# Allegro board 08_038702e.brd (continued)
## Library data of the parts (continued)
SW1 = SWSPST4PIN_V2: User Part Number: UPN; Tolerance: N/A; alternate symbols: (); part number: SWSPST4PIN_V2_SM-7914J-1-000E,E011086,SWSMSQ197H165; tolerance: N/A
T1-T8 = XFMRTCMXXXX_V3: Tolerance: N/A; User Part Number: UPN; alternate symbols: (); part number: XFMRTCMXXXX_V3_SM-TCM1-63AX+,E018203,TSML150W160H160; tolerance: N/A
TP2 = NCTESTPAD: Tolerance: N/A; User Part Number: UPN; alternate symbols: (); part number: NCTESTPAD_SM-TESTPAD,E012884,TPSMC30; tolerance: N/A
U1 = ICXC7Z035: Tolerance: N/A; User Part Number: UPN; alternate symbols: (); part number: ICXC7Z035_SM-XC7Z035-L2FBG676I,E022235,FBGA676; tolerance: N/A
U2 U3 = ICMT41K256M16: User Part Number: UPN; Tolerance: N/A; alternate symbols: (); part number: ICMT41K256M16_SM-MT41K256M16TW-107:P,E025442,FBGA96_C; tolerance: N/A
U4 = ADP5135: Tolerance: N/A; User Part Number: UPN; alternate symbols: (); part number: ADP5135_SM-ADP5135,E019805,QFN24_4X4_PAD2_6X2_6; tolerance: N/A
U5 = ADG772: User Part Number: UPN; Tolerance: N/A; alternate symbols: (); part number: ADG772_SM-ADG772BCPZ,E010354,QFN10_1_6X1_3; tolerance: N/A
U6 = ADP7102: Tolerance: N/A; User Part Number: UPN; alternate symbols: (); part number: ADP7102_SM-ADP7102ACPZ-2.5,E021467,QFN8_3X3_PAD2_44X1_7; tolerance: N/A
U7 = ADM1166: User Part Number: UPN; Tolerance: N/A; alternate symbols: (); part number: ADM1166_SM-ADM1166ACPZ,E016939,QFN40_6X6_PAD4_6X4_6; tolerance: N/A
U8 = ADM7160: User Part Number: UPN; Tolerance: N/A; alternate symbols: (); part number: ADM7160_SM-ADM7160AUJZ-1.8,E018469,TSOT-5; tolerance: N/A
U9 = ADP7104: Tolerance: N/A; User Part Number: UPN; alternate symbols: (); part number: ADP7104_SM-ADP7104ACPZ-3.3-R7,E014912,QFN8_3X3_PAD2_44X1_7; tolerance: N/A
U10 = IC88E151X: User Part Number: UPN; Tolerance: N/A; alternate symbols: (); part number: IC88E151X_SM-88E1512-56QFN,E018914,QFN56_8X8_PAD4_37X4_37; tolerance: N/A
U11 = ICTXS02612RTW: User Part Number: UPN; Tolerance: N/A; alternate symbols: (); part number: ICTXS02612RTW_SM-TXS02612RTWR,E021332,QFN24_4X4_PAD2_5X2_5; tolerance: N/A
U13 = ICN25Q256A_V2: User Part Number: UPN; Tolerance: N/A; alternate symbols: (); part number: ICN25Q256A_V2_SM-N25Q256A11E1240,E023338,TBGA24; tolerance: N/A
U14 = ICTPS51206: Tolerance: N/A; User Part Number: UPN; alternate symbols: (); part number: ICTPS51206_SM-TPS51206DSQR,E021346,SON10_2X2_PAD1_5X0_9; tolerance: N/A
U15 = ICUSB3320C: Tolerance: N/A; User Part Number: UPN; alternate symbols: (); part number: ICUSB3320C_SM-USB3320C-EZK,E021334,QFN32_5X5_PAD3_3X3_3; tolerance: N/A
U16 = DIO6P_V8: User Part Number: UPN; Tolerance: N/A; alternate symbols: (); part number: DIO6P_V8_SM-CDSOT23-SR208,20V,N/A,E021337,SOT23_6-2; tolerance: N/A
U17 = AD9361: Tolerance: N/A; User Part Number: UPN; alternate symbols: (); part number: AD9361_SM-AD9361BBCZ,E011827,BGA144; tolerance: N/A
U18 = ADP238X: User Part Number: UPN; Tolerance: N/A; alternate symbols: (); part number: ADP238X_SM-ADP2386ACPZN,E012985,QFN24_4X4_2PAD; tolerance: N/A
U19 U20 = ADP1754: Tolerance: N/A; User Part Number: UPN; alternate symbols: (); part number: ADP1754_SM-ADP1754ACPZ-1.3,E022696,QFN16_4X4_PAD2_1X2_1; tolerance: N/A
U21 = CMOSTCA9517: Tolerance: N/A; User Part Number: UPN; alternate symbols: (); part number: CMOSTCA9517_SM-TCA9517DGKR,E022173,MSOP8; tolerance: N/A
U22 = ICFXL4T245: Tolerance: N/A; User Part Number: UPN; alternate symbols: (); part number: ICFXL4T245_SM-FXL4T245BQX,E021654,DQFN14_3X2_5_PAD1_65X1_15; tolerance: N/A
U23 = ADP7118_V2: User Part Number: UPN; Tolerance: N/A; alternate symbols: (); part number: ADP7118_V2_SM-ADP7118AUJZ-3.3,E021874,TSOT-5; tolerance: N/A
U24 = AD7291: User Part Number: UPN; Tolerance: N/A; alternate symbols: (); part number: AD7291_SM-AD7291BCPZ,E017361,QFN20_4X4_PAD2_6X2_6; tolerance: N/A
Y1 = XTALOSC4P_V7: Tolerance: N/A; User Part Number: UPN; alternate symbols: (); part number: XTALOSC4P_V7_SM-33.333MEGHZ,E024048,YSML98W79H35; tolerance: N/A
Y2 = XTAL4PIN_V3: Tolerance: +/-20PPM; User Part Number: UPN; alternate symbols: (); part number: XTAL4PIN_V3_SM-25MEGHZ,E023420,YSML126W98H39; tolerance: +/-20PPM
Y3 = XTALOSC4P_V7: Tolerance: N/A; User Part Number: UPN; alternate symbols: (); part number: XTALOSC4P_V7_SM-24MEGHZ,E022374,YSML98W79H35; tolerance: N/A
Y4 = XTALOSC4P_V21: Tolerance: N/A; User Part Number: UPN; alternate symbols: (); part number: XTALOSC4P_V21_SM-40MEGHZ,E020493,YSML126W98H47; tolerance: N/A

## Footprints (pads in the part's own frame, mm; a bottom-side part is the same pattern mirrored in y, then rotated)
BGA144
  round 0.356 smd: A1(-4.4,-4.4) A2(-4.4,-3.6) A3(-4.4,-2.8) A4(-4.4,-2) A5(-4.4,-1.2) A6(-4.4,-0.4) A7(-4.4,0.4) A8(-4.4,1.2) A9(-4.4,2) A10(-4.4,2.8) A11(-4.4,3.6) A12(-4.4,4.4) B1(-3.6,-4.4) B2(-3.6,-3.6) B3(-3.6,-2.8) B4(-3.6,-2) B5(-3.6,-1.2) B6(-3.6,-0.4) B7(-3.6,0.4) B8(-3.6,1.2) B9(-3.6,2) B10(-3.6,2.8) B11(-3.6,3.6) B12(-3.6,4.4) C1(-2.8,-4.4) C2(-2.8,-3.6) C3(-2.8,-2.8) C4(-2.8,-2) C5(-2.8,-1.2) C6(-2.8,-0.4) C7(-2.8,0.4) C8(-2.8,1.2) C9(-2.8,2) C10(-2.8,2.8) C11(-2.8,3.6) C12(-2.8,4.4) D1(-2,-4.4) D2(-2,-3.6) D3(-2,-2.8) D4(-2,-2) D5(-2,-1.2) D6(-2,-0.4) D7(-2,0.4) D8(-2,1.2) D9(-2,2) D10(-2,2.8) D11(-2,3.6) D12(-2,4.4) E1(-1.2,-4.4) E2(-1.2,-3.6) E3(-1.2,-2.8) E4(-1.2,-2) E5(-1.2,-1.2) E6(-1.2,-0.4) E7(-1.2,0.4) E8(-1.2,1.2) E9(-1.2,2) E10(-1.2,2.8) E11(-1.2,3.6) E12(-1.2,4.4) F1(-0.4,-4.4) F2(-0.4,-3.6) F3(-0.4,-2.8) F4(-0.4,-2) F5(-0.4,-1.2) F6(-0.4,-0.4) F7(-0.4,0.4) F8(-0.4,1.2) F9(-0.4,2) F10(-0.4,2.8) F11(-0.4,3.6) F12(-0.4,4.4) G1(0.4,-4.4) G2(0.4,-3.6) G3(0.4,-2.8) G4(0.4,-2) G5(0.4,-1.2) G6(0.4,-0.4) G7(0.4,0.4) G8(0.4,1.2) G9(0.4,2) G10(0.4,2.8) G11(0.4,3.6) G12(0.4,4.4) H1(1.2,-4.4) H2(1.2,-3.6) H3(1.2,-2.8) H4(1.2,-2) H5(1.2,-1.2) H6(1.2,-0.4) H7(1.2,0.4) H8(1.2,1.2) H9(1.2,2) H10(1.2,2.8) H11(1.2,3.6) H12(1.2,4.4) J1(2,-4.4) J2(2,-3.6) J3(2,-2.8) J4(2,-2) J5(2,-1.2) J6(2,-0.4) J7(2,0.4) J8(2,1.2) J9(2,2) J10(2,2.8) J11(2,3.6) J12(2,4.4) K1(2.8,-4.4) K2(2.8,-3.6) K3(2.8,-2.8) K4(2.8,-2) K5(2.8,-1.2) K6(2.8,-0.4) K7(2.8,0.4) K8(2.8,1.2) K9(2.8,2) K10(2.8,2.8) K11(2.8,3.6) K12(2.8,4.4) L1(3.6,-4.4) L2(3.6,-3.6) L3(3.6,-2.8) L4(3.6,-2) L5(3.6,-1.2) L6(3.6,-0.4) L7(3.6,0.4) L8(3.6,1.2) L9(3.6,2) L10(3.6,2.8) L11(3.6,3.6) L12(3.6,4.4) M1(4.4,-4.4) M2(4.4,-3.6) M3(4.4,-2.8) M4(4.4,-2) M5(4.4,-1.2) M6(4.4,-0.4) M7(4.4,0.4) M8(4.4,1.2) M9(4.4,2) M10(4.4,2.8) M11(4.4,3.6) M12(4.4,4.4)
C0201
  rect 0.305x0.406 smd: 1(-0.318,0) 2(0.318,0)
C0402
  rect 0.889x0.813 smd: 1(-0.635,0) 2(0.635,0)
C0603
  rect 1.092x1.194 smd: 1(-0.851,0) 2(0.851,0)
C0805
  rect 1.295x1.6 smd: 1(-0.953,0) 2(0.953,0)
C0805H60
  rect 1.295x1.6 smd: 1(-0.953,0) 2(0.953,0)
C1206H71
  rect 1.6x2.007 smd: 1(-1.397,0) 2(1.397,0)
CNFCI61082-101400
  round 2.21 hole 1.194 unplated: (-22.1,0)
  round 1.905 hole 0.787 unplated: (22.1,0)
  rect 0.508x2.007 smd: 1(-19.6,-2.2) 2(-19.6,2.2) 3(-18.8,-2.2) 4(-18.8,2.2) 5(-18,-2.2) 6(-18,2.2) 7(-17.2,-2.2) 8(-17.2,2.2) 9(-16.4,-2.2) 10(-16.4,2.2) 11(-15.6,-2.2) 12(-15.6,2.2) 13(-14.8,-2.2) 14(-14.8,2.2) 15(-14,-2.2) 16(-14,2.2) 17(-13.2,-2.2) 18(-13.2,2.2) 19(-12.4,-2.2) 20(-12.4,2.2) 21(-11.6,-2.2) 22(-11.6,2.2) 23(-10.8,-2.2) 24(-10.8,2.2) 25(-10,-2.2) 26(-10,2.2) 27(-9.2,-2.2) 28(-9.2,2.2) 29(-8.4,-2.2) 30(-8.4,2.2) 31(-7.6,-2.2) 32(-7.6,2.2) 33(-6.8,-2.2) 34(-6.8,2.2) 35(-6,-2.2) 36(-6,2.2) 37(-5.2,-2.2) 38(-5.2,2.2) 39(-4.4,-2.2) 40(-4.4,2.2) 41(-3.6,-2.2) 42(-3.6,2.2) 43(-2.8,-2.2) 44(-2.8,2.2) 45(-2,-2.2) 46(-2,2.2) 47(-1.2,-2.2) 48(-1.2,2.2) 49(-0.4,-2.2) 50(-0.4,2.2) 51(0.4,-2.2) 52(0.4,2.2) 53(1.2,-2.2) 54(1.2,2.2) 55(2,-2.2) 56(2,2.2) 57(2.8,-2.2) 58(2.8,2.2) 59(3.6,-2.2) 60(3.6,2.2) 61(4.4,-2.2) 62(4.4,2.2) 63(5.2,-2.2) 64(5.2,2.2) 65(6,-2.2) 66(6,2.2) 67(6.8,-2.2) 68(6.8,2.2) 69(7.6,-2.2) 70(7.6,2.2) 71(8.4,-2.2) 72(8.4,2.2) 73(9.2,-2.2) 74(9.2,2.2) 75(10,-2.2) 76(10,2.2) 77(10.8,-2.2) 78(10.8,2.2) 79(11.6,-2.2) 80(11.6,2.2) 81(12.4,-2.2) 82(12.4,2.2) 83(13.2,-2.2) 84(13.2,2.2) 85(14,-2.2) 86(14,2.2) 87(14.8,-2.2) 88(14.8,2.2) 89(15.6,-2.2) 90(15.6,2.2) 91(16.4,-2.2) 92(16.4,2.2) 93(17.2,-2.2) 94(17.2,2.2) 95(18,-2.2) 96(18,2.2) 97(18.8,-2.2) 98(18.8,2.2) 99(19.6,-2.2) 100(19.6,2.2)
CNHIROSE-U_FL-R-SMT-1
  rect 0.991x1.041 smd: 1(0,-1.521)
  rect 1.041x2.21 smd: 2(-1.471,0) 3(1.471,0)
CNHIROSEDM3CS-SF
  rect 2.007x0.711 smd: 1(-6.204,-3.2) 2(-6.204,-2.1) 3(-6.204,-1) 4(-6.204,0.1) 5(-6.204,1.2) 6(-6.204,2.3) 7(-6.204,3.4) 8(-6.204,4.5)
  rect 1.397x2.692 smd: 9(6.5,-1.8) GND3(6.5,3.1)
  rect 2.591x1.499 smd: GND1(-5.7,-6.75)
  rect 1.194x1.194 smd: GND2(6.6,-4.85)
  rect 2.591x0.991 smd: GND4(-5.7,6.6)
CNTE5147733-4
  rect 1.524x2.286 smd: A1(-5.08,-4.52) A2(-2.54,-4.52) A3(0,-4.52) A4(2.54,-4.52) A5(5.08,-4.52) B1(-5.08,4.52) B2(-2.54,4.52) B3(0,4.52) B4(2.54,4.52) B5(5.08,4.52)
CPLSML287W169H118
  rect 2.388x2.896 smd: N(3.044,0) P(-3.044,0)
DQFN14_3X2_5_PAD1_65X1_15
  oval 0.914x0.254 smd: 1(-1.557,-0.25) 7(1.557,-0.25) 8(1.557,0.25) 14(-1.557,0.25)
  oval 0.254x0.914 smd: 2(-1,-1.307) 3(-0.5,-1.307) 4(0,-1.307) 5(0.5,-1.307) 6(1,-1.307) 9(1,1.307) 10(0.5,1.307) 11(0,1.307) 12(-0.5,1.307) 13(-1,1.307)
  rect 1.651x1.143 smd: PAD(0,0)
FBGA96_C
  round 0.381 smd: A1(-6,-3.2) A2(-6,-2.4) A3(-6,-1.6) A7(-6,1.6) A8(-6,2.4) A9(-6,3.2) B1(-5.2,-3.2) B2(-5.2,-2.4) B3(-5.2,-1.6) B7(-5.2,1.6) B8(-5.2,2.4) B9(-5.2,3.2) C1(-4.4,-3.2) C2(-4.4,-2.4) C3(-4.4,-1.6) C7(-4.4,1.6) C8(-4.4,2.4) C9(-4.4,3.2) D1(-3.6,-3.2) D2(-3.6,-2.4) D3(-3.6,-1.6) D7(-3.6,1.6) D8(-3.6,2.4) D9(-3.6,3.2) E1(-2.8,-3.2) E2(-2.8,-2.4) E3(-2.8,-1.6) E7(-2.8,1.6) E8(-2.8,2.4) E9(-2.8,3.2) F1(-2,-3.2) F2(-2,-2.4) F3(-2,-1.6) F7(-2,1.6) F8(-2,2.4) F9(-2,3.2) G1(-1.2,-3.2) G2(-1.2,-2.4) G3(-1.2,-1.6) G7(-1.2,1.6) G8(-1.2,2.4) G9(-1.2,3.2) H1(-0.4,-3.2) H2(-0.4,-2.4) H3(-0.4,-1.6) H7(-0.4,1.6) H8(-0.4,2.4) H9(-0.4,3.2) J1(0.4,-3.2) J2(0.4,-2.4) J3(0.4,-1.6) J7(0.4,1.6) J8(0.4,2.4) J9(0.4,3.2) K1(1.2,-3.2) K2(1.2,-2.4) K3(1.2,-1.6) K7(1.2,1.6) K8(1.2,2.4) K9(1.2,3.2) L1(2,-3.2) L2(2,-2.4) L3(2,-1.6) L7(2,1.6) L8(2,2.4) L9(2,3.2) M1(2.8,-3.2) M2(2.8,-2.4) M3(2.8,-1.6) M7(2.8,1.6) M8(2.8,2.4) M9(2.8,3.2) N1(3.6,-3.2) N2(3.6,-2.4) N3(3.6,-1.6) N7(3.6,1.6) N8(3.6,2.4) N9(3.6,3.2) P1(4.4,-3.2) P2(4.4,-2.4) P3(4.4,-1.6) P7(4.4,1.6) P8(4.4,2.4) P9(4.4,3.2) R1(5.2,-3.2) R2(5.2,-2.4) R3(5.2,-1.6) R7(5.2,1.6) R8(5.2,2.4) R9(5.2,3.2) T1(6,-3.2) T2(6,-2.4) T3(6,-1.6) T7(6,1.6) T8(6,2.4) T9(6,3.2)
FBGA676
  round 0.457 smd: A1(-12.5,-12.5) A2(-12.5,-11.5) A3(-12.5,-10.5) A4(-12.5,-9.5) A5(-12.5,-8.5) A6(-12.5,-7.5) A7(-12.5,-6.5) A8(-12.5,-5.5) A9(-12.5,-4.5) A10(-12.5,-3.5) A11(-12.5,-2.5) A12(-12.5,-1.5) A13(-12.5,-0.5) A14(-12.5,0.5) A15(-12.5,1.5) A16(-12.5,2.5) A17(-12.5,3.5) A18(-12.5,4.5) A19(-12.5,5.5) A20(-12.5,6.5) A21(-12.5,7.5) A22(-12.5,8.5) A23(-12.5,9.5) A24(-12.5,10.5) A25(-12.5,11.5) A26(-12.5,12.5) AA1(7.5,-12.5) AA2(7.5,-11.5) AA3(7.5,-10.5) AA4(7.5,-9.5) AA5(7.5,-8.5) AA6(7.5,-7.5) AA7(7.5,-6.5) AA8(7.5,-5.5) AA9(7.5,-4.5) AA10(7.5,-3.5) AA11(7.5,-2.5) AA12(7.5,-1.5) AA13(7.5,-0.5) AA14(7.5,0.5) AA15(7.5,1.5) AA16(7.5,2.5) AA17(7.5,3.5) AA18(7.5,4.5) AA19(7.5,5.5) AA20(7.5,6.5) AA21(7.5,7.5) AA22(7.5,8.5) AA23(7.5,9.5) AA24(7.5,10.5) AA25(7.5,11.5) AA26(7.5,12.5) AB1(8.5,-12.5) AB2(8.5,-11.5) AB3(8.5,-10.5) AB4(8.5,-9.5) AB5(8.5,-8.5) AB6(8.5,-7.5) AB7(8.5,-6.5) AB8(8.5,-5.5) AB9(8.5,-4.5) AB10(8.5,-3.5) AB11(8.5,-2.5) AB12(8.5,-1.5) AB13(8.5,-0.5) AB14(8.5,0.5) AB15(8.5,1.5) AB16(8.5,2.5) AB17(8.5,3.5) AB18(8.5,4.5) AB19(8.5,5.5) AB20(8.5,6.5) AB21(8.5,7.5) AB22(8.5,8.5) AB23(8.5,9.5) AB24(8.5,10.5) AB25(8.5,11.5) AB26(8.5,12.5) AC1(9.5,-12.5) AC2(9.5,-11.5) AC3(9.5,-10.5) AC4(9.5,-9.5) AC5(9.5,-8.5) AC6(9.5,-7.5) AC7(9.5,-6.5) AC8(9.5,-5.5) AC9(9.5,-4.5) AC10(9.5,-3.5) AC11(9.5,-2.5) AC12(9.5,-1.5) AC13(9.5,-0.5) AC14(9.5,0.5) AC15(9.5,1.5) AC16(9.5,2.5) AC17(9.5,3.5) AC18(9.5,4.5) AC19(9.5,5.5) AC20(9.5,6.5) AC21(9.5,7.5) AC22(9.5,8.5) AC23(9.5,9.5) AC24(9.5,10.5) AC25(9.5,11.5) AC26(9.5,12.5) AD1(10.5,-12.5) AD2(10.5,-11.5) AD3(10.5,-10.5) AD4(10.5,-9.5) AD5(10.5,-8.5) AD6(10.5,-7.5) AD7(10.5,-6.5) AD8(10.5,-5.5) AD9(10.5,-4.5) AD10(10.5,-3.5) AD11(10.5,-2.5) AD12(10.5,-1.5) AD13(10.5,-0.5) AD14(10.5,0.5) AD15(10.5,1.5) AD16(10.5,2.5) AD17(10.5,3.5) AD18(10.5,4.5) AD19(10.5,5.5) AD20(10.5,6.5) AD21(10.5,7.5) AD22(10.5,8.5) AD23(10.5,9.5) AD24(10.5,10.5) AD25(10.5,11.5) AD26(10.5,12.5) AE1(11.5,-12.5) AE2(11.5,-11.5) AE3(11.5,-10.5) AE4(11.5,-9.5) AE5(11.5,-8.5) AE6(11.5,-7.5) AE7(11.5,-6.5) AE8(11.5,-5.5) AE9(11.5,-4.5) AE10(11.5,-3.5) AE11(11.5,-2.5) AE12(11.5,-1.5) AE13(11.5,-0.5) AE14(11.5,0.5) AE15(11.5,1.5) AE16(11.5,2.5) AE17(11.5,3.5) AE18(11.5,4.5) AE19(11.5,5.5) AE20(11.5,6.5) AE21(11.5,7.5) AE22(11.5,8.5) AE23(11.5,9.5) AE24(11.5,10.5) AE25(11.5,11.5) AE26(11.5,12.5) AF1(12.5,-12.5) AF2(12.5,-11.5) AF3(12.5,-10.5) AF4(12.5,-9.5) AF5(12.5,-8.5) AF6(12.5,-7.5) AF7(12.5,-6.5) AF8(12.5,-5.5) AF9(12.5,-4.5) AF10(12.5,-3.5) AF11(12.5,-2.5) AF12(12.5,-1.5) AF13(12.5,-0.5) AF14(12.5,0.5) AF15(12.5,1.5) AF16(12.5,2.5) AF17(12.5,3.5) AF18(12.5,4.5) AF19(12.5,5.5) AF20(12.5,6.5) AF21(12.5,7.5) AF22(12.5,8.5) AF23(12.5,9.5) AF24(12.5,10.5) AF25(12.5,11.5) AF26(12.5,12.5) B1(-11.5,-12.5) B2(-11.5,-11.5) B3(-11.5,-10.5) B4(-11.5,-9.5) B5(-11.5,-8.5) B6(-11.5,-7.5) B7(-11.5,-6.5) B8(-11.5,-5.5) B9(-11.5,-4.5) B10(-11.5,-3.5) B11(-11.5,-2.5) B12(-11.5,-1.5) B13(-11.5,-0.5) B14(-11.5,0.5) B15(-11.5,1.5) B16(-11.5,2.5) B17(-11.5,3.5) B18(-11.5,4.5) B19(-11.5,5.5) B20(-11.5,6.5) B21(-11.5,7.5) B22(-11.5,8.5) B23(-11.5,9.5) B24(-11.5,10.5) B25(-11.5,11.5) B26(-11.5,12.5) C1(-10.5,-12.5) C2(-10.5,-11.5) C3(-10.5,-10.5) C4(-10.5,-9.5) C5(-10.5,-8.5) C6(-10.5,-7.5) C7(-10.5,-6.5) C8(-10.5,-5.5) C9(-10.5,-4.5) C10(-10.5,-3.5) C11(-10.5,-2.5) C12(-10.5,-1.5) C13(-10.5,-0.5) C14(-10.5,0.5) C15(-10.5,1.5) C16(-10.5,2.5) C17(-10.5,3.5) C18(-10.5,4.5) C19(-10.5,5.5) C20(-10.5,6.5) C21(-10.5,7.5) C22(-10.5,8.5) C23(-10.5,9.5) C24(-10.5,10.5) C25(-10.5,11.5) C26(-10.5,12.5) D1(-9.5,-12.5) D2(-9.5,-11.5) D3(-9.5,-10.5) D4(-9.5,-9.5) D5(-9.5,-8.5) D6(-9.5,-7.5) D7(-9.5,-6.5) D8(-9.5,-5.5) D9(-9.5,-4.5) D10(-9.5,-3.5) D11(-9.5,-2.5) D12(-9.5,-1.5) D13(-9.5,-0.5) D14(-9.5,0.5) D15(-9.5,1.5) D16(-9.5,2.5) D17(-9.5,3.5) D18(-9.5,4.5) D19(-9.5,5.5) D20(-9.5,6.5) D21(-9.5,7.5) D22(-9.5,8.5) D23(-9.5,9.5) D24(-9.5,10.5) D25(-9.5,11.5) D26(-9.5,12.5) E1(-8.5,-12.5) E2(-8.5,-11.5) E3(-8.5,-10.5) E4(-8.5,-9.5) E5(-8.5,-8.5) E6(-8.5,-7.5) E7(-8.5,-6.5) E8(-8.5,-5.5) E9(-8.5,-4.5) E10(-8.5,-3.5) E11(-8.5,-2.5) E12(-8.5,-1.5) E13(-8.5,-0.5) E14(-8.5,0.5) E15(-8.5,1.5) E16(-8.5,2.5) E17(-8.5,3.5) E18(-8.5,4.5) E19(-8.5,5.5) E20(-8.5,6.5) E21(-8.5,7.5) E22(-8.5,8.5) E23(-8.5,9.5) E24(-8.5,10.5) E25(-8.5,11.5) E26(-8.5,12.5) F1(-7.5,-12.5) F2(-7.5,-11.5) F3(-7.5,-10.5) F4(-7.5,-9.5) F5(-7.5,-8.5) F6(-7.5,-7.5) F7(-7.5,-6.5) F8(-7.5,-5.5) F9(-7.5,-4.5) F10(-7.5,-3.5) F11(-7.5,-2.5) F12(-7.5,-1.5) F13(-7.5,-0.5) F14(-7.5,0.5) F15(-7.5,1.5) F16(-7.5,2.5) F17(-7.5,3.5) F18(-7.5,4.5) F19(-7.5,5.5) F20(-7.5,6.5) F21(-7.5,7.5) F22(-7.5,8.5) F23(-7.5,9.5) F24(-7.5,10.5) F25(-7.5,11.5) F26(-7.5,12.5) G1(-6.5,-12.5) G2(-6.5,-11.5) G3(-6.5,-10.5) G4(-6.5,-9.5) G5(-6.5,-8.5) G6(-6.5,-7.5) G7(-6.5,-6.5) G8(-6.5,-5.5) G9(-6.5,-4.5) G10(-6.5,-3.5) G11(-6.5,-2.5) G12(-6.5,-1.5) G13(-6.5,-0.5) G14(-6.5,0.5) G15(-6.5,1.5) G16(-6.5,2.5) G17(-6.5,3.5) G18(-6.5,4.5) G19(-6.5,5.5) G20(-6.5,6.5) G21(-6.5,7.5) G22(-6.5,8.5) G23(-6.5,9.5) G24(-6.5,10.5) G25(-6.5,11.5) G26(-6.5,12.5) H1(-5.5,-12.5) H2(-5.5,-11.5) H3(-5.5,-10.5) H4(-5.5,-9.5) H5(-5.5,-8.5) H6(-5.5,-7.5) H7(-5.5,-6.5) H8(-5.5,-5.5) H9(-5.5,-4.5) H10(-5.5,-3.5) H11(-5.5,-2.5) H12(-5.5,-1.5) H13(-5.5,-0.5) H14(-5.5,0.5) H15(-5.5,1.5) H16(-5.5,2.5) H17(-5.5,3.5) H18(-5.5,4.5) H19(-5.5,5.5) H20(-5.5,6.5) H21(-5.5,7.5) H22(-5.5,8.5) H23(-5.5,9.5) H24(-5.5,10.5) H25(-5.5,11.5) H26(-5.5,12.5) J1(-4.5,-12.5) J2(-4.5,-11.5) J3(-4.5,-10.5) J4(-4.5,-9.5) J5(-4.5,-8.5) J6(-4.5,-7.5) J7(-4.5,-6.5) J8(-4.5,-5.5) J9(-4.5,-4.5) J10(-4.5,-3.5) J11(-4.5,-2.5) J12(-4.5,-1.5) J13(-4.5,-0.5) J14(-4.5,0.5) J15(-4.5,1.5) J16(-4.5,2.5) J17(-4.5,3.5) J18(-4.5,4.5) J19(-4.5,5.5) J20(-4.5,6.5) J21(-4.5,7.5) J22(-4.5,8.5) J23(-4.5,9.5) J24(-4.5,10.5) J25(-4.5,11.5) J26(-4.5,12.5) K1(-3.5,-12.5) K2(-3.5,-11.5) K3(-3.5,-10.5) K4(-3.5,-9.5) K5(-3.5,-8.5) K6(-3.5,-7.5) K7(-3.5,-6.5) K8(-3.5,-5.5) K9(-3.5,-4.5) K10(-3.5,-3.5) K11(-3.5,-2.5) K12(-3.5,-1.5) K13(-3.5,-0.5) K14(-3.5,0.5) K15(-3.5,1.5) K16(-3.5,2.5) K17(-3.5,3.5) K18(-3.5,4.5) K19(-3.5,5.5) K20(-3.5,6.5) K21(-3.5,7.5) K22(-3.5,8.5) K23(-3.5,9.5) K24(-3.5,10.5) K25(-3.5,11.5) K26(-3.5,12.5) L1(-2.5,-12.5) L2(-2.5,-11.5) L3(-2.5,-10.5) L4(-2.5,-9.5) L5(-2.5,-8.5) L6(-2.5,-7.5) L7(-2.5,-6.5) L8(-2.5,-5.5) L9(-2.5,-4.5) L10(-2.5,-3.5) L11(-2.5,-2.5) L12(-2.5,-1.5) L13(-2.5,-0.5) L14(-2.5,0.5) L15(-2.5,1.5) L16(-2.5,2.5) L17(-2.5,3.5) L18(-2.5,4.5) L19(-2.5,5.5) L20(-2.5,6.5) L21(-2.5,7.5) L22(-2.5,8.5) L23(-2.5,9.5) L24(-2.5,10.5) L25(-2.5,11.5) L26(-2.5,12.5) M1(-1.5,-12.5) M2(-1.5,-11.5) M3(-1.5,-10.5) M4(-1.5,-9.5) M5(-1.5,-8.5) M6(-1.5,-7.5) M7(-1.5,-6.5) M8(-1.5,-5.5) M9(-1.5,-4.5) M10(-1.5,-3.5) M11(-1.5,-2.5) M12(-1.5,-1.5) M13(-1.5,-0.5) M14(-1.5,0.5) M15(-1.5,1.5) M16(-1.5,2.5) M17(-1.5,3.5) M18(-1.5,4.5) M19(-1.5,5.5) M20(-1.5,6.5) M21(-1.5,7.5) M22(-1.5,8.5) M23(-1.5,9.5) M24(-1.5,10.5) M25(-1.5,11.5) M26(-1.5,12.5) N1(-0.5,-12.5) N2(-0.5,-11.5) N3(-0.5,-10.5) N4(-0.5,-9.5) N5(-0.5,-8.5) N6(-0.5,-7.5) N7(-0.5,-6.5) N8(-0.5,-5.5) N9(-0.5,-4.5) N10(-0.5,-3.5) N11(-0.5,-2.5) N12(-0.5,-1.5) N13(-0.5,-0.5) N14(-0.5,0.5) N15(-0.5,1.5) N16(-0.5,2.5) N17(-0.5,3.5) N18(-0.5,4.5) N19(-0.5,5.5) N20(-0.5,6.5) N21(-0.5,7.5) N22(-0.5,8.5) N23(-0.5,9.5) N24(-0.5,10.5) N25(-0.5,11.5) N26(-0.5,12.5) P1(0.5,-12.5) P2(0.5,-11.5) P3(0.5,-10.5) P4(0.5,-9.5) P5(0.5,-8.5) P6(0.5,-7.5) P7(0.5,-6.5) P8(0.5,-5.5) P9(0.5,-4.5) P10(0.5,-3.5) P11(0.5,-2.5) P12(0.5,-1.5) P13(0.5,-0.5) P14(0.5,0.5) P15(0.5,1.5) P16(0.5,2.5) P17(0.5,3.5) P18(0.5,4.5) P19(0.5,5.5) P20(0.5,6.5) P21(0.5,7.5) P22(0.5,8.5) P23(0.5,9.5) P24(0.5,10.5) P25(0.5,11.5) P26(0.5,12.5) R1(1.5,-12.5) R2(1.5,-11.5) R3(1.5,-10.5) R4(1.5,-9.5) R5(1.5,-8.5) R6(1.5,-7.5) R7(1.5,-6.5) R8(1.5,-5.5) R9(1.5,-4.5) R10(1.5,-3.5) R11(1.5,-2.5) R12(1.5,-1.5) R13(1.5,-0.5) R14(1.5,0.5) R15(1.5,1.5) R16(1.5,2.5) R17(1.5,3.5) R18(1.5,4.5) R19(1.5,5.5) R20(1.5,6.5) R21(1.5,7.5) R22(1.5,8.5) R23(1.5,9.5) R24(1.5,10.5) R25(1.5,11.5) R26(1.5,12.5) T1(2.5,-12.5) T2(2.5,-11.5) T3(2.5,-10.5) T4(2.5,-9.5) T5(2.5,-8.5) T6(2.5,-7.5) T7(2.5,-6.5) T8(2.5,-5.5) T9(2.5,-4.5) T10(2.5,-3.5) T11(2.5,-2.5) T12(2.5,-1.5) T13(2.5,-0.5) T14(2.5,0.5) T15(2.5,1.5) T16(2.5,2.5) T17(2.5,3.5) T18(2.5,4.5) T19(2.5,5.5) T20(2.5,6.5) T21(2.5,7.5) T22(2.5,8.5) T23(2.5,9.5) T24(2.5,10.5) T25(2.5,11.5) T26(2.5,12.5) U1(3.5,-12.5) U2(3.5,-11.5) U3(3.5,-10.5) U4(3.5,-9.5) U5(3.5,-8.5) U6(3.5,-7.5) U7(3.5,-6.5) U8(3.5,-5.5) U9(3.5,-4.5) U10(3.5,-3.5) U11(3.5,-2.5) U12(3.5,-1.5) U13(3.5,-0.5) U14(3.5,0.5) U15(3.5,1.5) U16(3.5,2.5) U17(3.5,3.5) U18(3.5,4.5) U19(3.5,5.5) U20(3.5,6.5) U21(3.5,7.5) U22(3.5,8.5) U23(3.5,9.5) U24(3.5,10.5) U25(3.5,11.5) U26(3.5,12.5) V1(4.5,-12.5) V2(4.5,-11.5) V3(4.5,-10.5) V4(4.5,-9.5) V5(4.5,-8.5) V6(4.5,-7.5) V7(4.5,-6.5) V8(4.5,-5.5) V9(4.5,-4.5) V10(4.5,-3.5) V11(4.5,-2.5) V12(4.5,-1.5) V13(4.5,-0.5) V14(4.5,0.5) V15(4.5,1.5) V16(4.5,2.5) V17(4.5,3.5) V18(4.5,4.5) V19(4.5,5.5) V20(4.5,6.5) V21(4.5,7.5) V22(4.5,8.5) V23(4.5,9.5) V24(4.5,10.5) V25(4.5,11.5) V26(4.5,12.5) W1(5.5,-12.5) W2(5.5,-11.5) W3(5.5,-10.5) W4(5.5,-9.5) W5(5.5,-8.5) W6(5.5,-7.5) W7(5.5,-6.5) W8(5.5,-5.5) W9(5.5,-4.5) W10(5.5,-3.5) W11(5.5,-2.5) W12(5.5,-1.5) W13(5.5,-0.5) W14(5.5,0.5) W15(5.5,1.5) W16(5.5,2.5) W17(5.5,3.5) W18(5.5,4.5) W19(5.5,5.5) W20(5.5,6.5) W21(5.5,7.5) W22(5.5,8.5) W23(5.5,9.5) W24(5.5,10.5) W25(5.5,11.5) W26(5.5,12.5) Y1(6.5,-12.5) Y2(6.5,-11.5) Y3(6.5,-10.5) Y4(6.5,-9.5) Y5(6.5,-8.5) Y6(6.5,-7.5) Y7(6.5,-6.5) Y8(6.5,-5.5) Y9(6.5,-4.5) Y10(6.5,-3.5) Y11(6.5,-2.5) Y12(6.5,-1.5) Y13(6.5,-0.5) Y14(6.5,0.5) Y15(6.5,1.5) Y16(6.5,2.5) Y17(6.5,3.5) Y18(6.5,4.5) Y19(6.5,5.5) Y20(6.5,6.5) Y21(6.5,7.5) Y22(6.5,8.5) Y23(6.5,9.5) Y24(6.5,10.5) Y25(6.5,11.5) Y26(6.5,12.5)
JPRSLD03
  rect 0.61x1.524 smd: 1(-0.838,0) 2(0,0) 3(0.838,0)
L0402
  rect 0.889x0.813 smd: 1(-0.635,0) 2(0.635,0)
L0603
  rect 0.889x0.813 smd: 1(-0.737,0) 2(0.737,0)
L0805
  rect 1.143x1.27 smd: 1(-0.953,0) 2(0.953,0)
L0805-F
  rect 1.092x1.499 smd: 1(-1.046,0) 2(1.046,0)
LED0603-2
  rect 0.787x0.787 smd: A(0.787,0) C(-0.787,0)
LSMSQ118H47
  rect 0.991x3.2 smd: 1(-0.995,0) 2(0.995,0)
LSMSQ157H63
  rect 0.965x3.404 smd: 1(-1.181,0) 2(1.181,0)
MLP6_2X2_PAD_9X1_PAD_2X_56
  rect 0.406x0.483 smd: 1(-0.65,-0.909) 2(0,-0.909) 3(0.65,-0.909) 4(0.65,0.909) 5(0,0.909) 6(-0.65,0.909)
  rect 1.041x0.991 smd: PAD1(-0.321,0)
  rect 0.406x0.66 smd: PAD2(0.653,0)
MLT15CCC2243A
  rect 3.15x1.016 smd: GND1(-11.455,-13.538) GND3(-0.279,-13.538) GND4(5.309,-13.538) GND5(10.897,-13.538) GND11(10.897,13.538) GND12(5.309,13.538) GND13(-0.279,13.538) GND14(-5.867,13.538) GND15(-11.455,13.538)
  rect 2.743x0.991 smd: GND2(-5.867,-13.538)
  rect 1.016x3.15 smd: GND6(14.148,-9.728) GND7(14.148,-5.029) GND8(14.148,-0.33) GND9(14.148,4.369) GND10(14.148,9.068) GND16(-14.148,7.925) GND17(-14.148,0)
  rect 0.991x2.743 smd: GND18(-14.148,-7.925)
  rect 4.572x1.016 smd: GND19(-10.135,0)
  rect 1.016x1.88 smd: GND20(-5.867,5.486) GND22(-5.867,-6.756)
  rect 1.016x4.572 smd: GND21(-5.867,0)
MSOP8
  rect 0.305x1.321 smd: 1(-0.975,-2.3) 2(-0.325,-2.3) 3(0.325,-2.3) 4(0.975,-2.3) 5(0.975,2.3) 6(0.325,2.3) 7(-0.325,2.3) 8(-0.975,2.3)
QFN8_3X3_PAD2_44X1_7
  oval 0.305x0.914 smd: 1(-0.75,-1.557) 2(-0.25,-1.557) 3(0.25,-1.557) 4(0.75,-1.557) 5(0.75,1.557) 6(0.25,1.557) 7(-0.25,1.557) 8(-0.75,1.557)
  rect 2.438x1.702 smd: PAD(0,0)
QFN10_1_6X1_3
  oval 0.61x0.203 smd: 1(-0.8,-0.4) 4(0.8,-0.4) 5(0.8,0) 6(0.8,0.4) 9(-0.8,0.4) 10(-0.8,0)
  oval 0.203x0.813 smd: 2(-0.2,-0.65) 3(0.2,-0.65) 7(0.2,0.65) 8(-0.2,0.65)
QFN16_4X4_PAD2_1X2_1
  oval 0.356x1.041 smd: 1(-0.975,-1.9) 2(-0.325,-1.9) 3(0.325,-1.9) 4(0.975,-1.9) 9(0.975,1.9) 10(0.325,1.9) 11(-0.325,1.9) 12(-0.975,1.9)
  oval 1.041x0.356 smd: 5(1.9,-0.975) 6(1.9,-0.325) 7(1.9,0.325) 8(1.9,0.975) 13(-1.9,0.975) 14(-1.9,0.325) 15(-1.9,-0.325) 16(-1.9,-0.975)
  rect 2.108x2.108 smd: PAD(0,0)
QFN20_4X4_PAD2_6X2_6
  oval 0.305x1.041 smd: 1(-1,-2.019) 2(-0.5,-2.019) 3(0,-2.019) 4(0.5,-2.019) 5(1,-2.019) 11(1,2.019) 12(0.5,2.019) 13(0,2.019) 14(-0.5,2.019) 15(-1,2.019)
  oval 1.041x0.305 smd: 6(2.019,-1) 7(2.019,-0.5) 8(2.019,0) 9(2.019,0.5) 10(2.019,1) 16(-2.019,1) 17(-2.019,0.5) 18(-2.019,0) 19(-2.019,-0.5) 20(-2.019,-1)
  rect 2.591x2.591 smd: PAD(0,0)
QFN24_4X4_2PAD
  oval 0.305x0.889 smd: 1(-1.25,-2.05) 2(-0.75,-2.05) 3(-0.25,-2.05) 4(0.25,-2.05) 5(0.75,-2.05) 6(1.25,-2.05) 13(1.25,2.05) 14(0.75,2.05) 15(0.25,2.05) 16(-0.25,2.05) 17(-0.75,2.05) 18(-1.25,2.05)
  oval 0.889x0.305 smd: 7(2.05,-1.25) 8(2.05,-0.75) 9(2.05,-0.25) 10(2.05,0.25) 11(2.05,0.75) 12(2.05,1.25) 19(-2.05,1.25) 20(-2.05,0.75) 21(-2.05,0.25) 22(-2.05,-0.25) 23(-2.05,-0.75) 24(-2.05,-1.25)
  rect 1.397x2.692 smd: PAD1(-0.648,0)
  rect 0.94x2.692 smd: PAD2(0.876,0)
QFN24_4X4_PAD2_5X2_5
  oval 0.305x0.991 smd: 1(-1.25,-2) 2(-0.75,-2) 3(-0.25,-2) 4(0.25,-2) 5(0.75,-2) 6(1.25,-2) 13(1.25,2) 14(0.75,2) 15(0.25,2) 16(-0.25,2) 17(-0.75,2) 18(-1.25,2)
  oval 0.991x0.305 smd: 7(2,-1.25) 8(2,-0.75) 9(2,-0.25) 10(2,0.25) 11(2,0.75) 12(2,1.25) 19(-2,1.25) 20(-2,0.75) 21(-2,0.25) 22(-2,-0.25) 23(-2,-0.75) 24(-2,-1.25)
  rect 2.489x2.489 smd: PAD(0,0)
QFN24_4X4_PAD2_6X2_6
  oval 0.305x0.838 smd: 1(-1.25,-1.95) 2(-0.75,-1.95) 3(-0.25,-1.95) 4(0.25,-1.95) 5(0.75,-1.95) 6(1.25,-1.95) 13(1.25,1.95) 14(0.75,1.95) 15(0.25,1.95) 16(-0.25,1.95) 17(-0.75,1.95) 18(-1.25,1.95)
  oval 0.838x0.305 smd: 7(1.95,-1.25) 8(1.95,-0.75) 9(1.95,-0.25) 10(1.95,0.25) 11(1.95,0.75) 12(1.95,1.25) 19(-1.95,1.25) 20(-1.95,0.75) 21(-1.95,0.25) 22(-1.95,-0.25) 23(-1.95,-0.75) 24(-1.95,-1.25)
  rect 2.591x2.591 smd: PAD(0,0)
QFN32_5X5_PAD3_3X3_3
  oval 0.305x0.889 smd: 1(-1.75,-2.45) 2(-1.25,-2.45) 3(-0.75,-2.45) 4(-0.25,-2.45) 5(0.25,-2.45) 6(0.75,-2.45) 7(1.25,-2.45) 8(1.75,-2.45) 17(1.75,2.45) 18(1.25,2.45) 19(0.75,2.45) 20(0.25,2.45) 21(-0.25,2.45) 22(-0.75,2.45) 23(-1.25,2.45) 24(-1.75,2.45)
  oval 0.889x0.305 smd: 9(2.45,-1.75) 10(2.45,-1.25) 11(2.45,-0.75) 12(2.45,-0.25) 13(2.45,0.25) 14(2.45,0.75) 15(2.45,1.25) 16(2.45,1.75) 25(-2.45,1.75) 26(-2.45,1.25) 27(-2.45,0.75) 28(-2.45,0.25) 29(-2.45,-0.25) 30(-2.45,-0.75) 31(-2.45,-1.25) 32(-2.45,-1.75)
  rect 3.302x3.302 smd: PAD(0,0)
QFN40_6X6_PAD4_6X4_6
  oval 0.305x0.94 smd: 1(-2.25,-3.005) 2(-1.75,-3.005) 3(-1.25,-3.005) 4(-0.75,-3.005) 5(-0.25,-3.005) 6(0.25,-3.005) 7(0.75,-3.005) 8(1.25,-3.005) 9(1.75,-3.005) 10(2.25,-3.005) 21(2.25,3.005) 22(1.75,3.005) 23(1.25,3.005) 24(0.75,3.005) 25(0.25,3.005) 26(-0.25,3.005) 27(-0.75,3.005) 28(-1.25,3.005) 29(-1.75,3.005) 30(-2.25,3.005)
  oval 0.94x0.305 smd: 11(3.005,-2.25) 12(3.005,-1.75) 13(3.005,-1.25) 14(3.005,-0.75) 15(3.005,-0.25) 16(3.005,0.25) 17(3.005,0.75) 18(3.005,1.25) 19(3.005,1.75) 20(3.005,2.25) 31(-3.005,2.25) 32(-3.005,1.75) 33(-3.005,1.25) 34(-3.005,0.75) 35(-3.005,0.25) 36(-3.005,-0.25) 37(-3.005,-0.75) 38(-3.005,-1.25) 39(-3.005,-1.75) 40(-3.005,-2.25)
  rect 4.597x4.597 smd: PAD(0,0)
QFN56_8X8_PAD4_37X4_37
  oval 0.305x0.838 smd: 1(-3.25,-3.95) 2(-2.75,-3.95) 3(-2.25,-3.95) 4(-1.75,-3.95) 5(-1.25,-3.95) 6(-0.75,-3.95) 7(-0.25,-3.95) 8(0.25,-3.95) 9(0.75,-3.95) 10(1.25,-3.95) 11(1.75,-3.95) 12(2.25,-3.95) 13(2.75,-3.95) 14(3.25,-3.95) 29(3.25,3.95) 30(2.75,3.95) 31(2.25,3.95) 32(1.75,3.95) 33(1.25,3.95) 34(0.75,3.95) 35(0.25,3.95) 36(-0.25,3.95) 37(-0.75,3.95) 38(-1.25,3.95) 39(-1.75,3.95) 40(-2.25,3.95) 41(-2.75,3.95) 42(-3.25,3.95)
  oval 0.838x0.305 smd: 15(3.95,-3.25) 16(3.95,-2.75) 17(3.95,-2.25) 18(3.95,-1.75) 19(3.95,-1.25) 20(3.95,-0.75) 21(3.95,-0.25) 22(3.95,0.25) 23(3.95,0.75) 24(3.95,1.25) 25(3.95,1.75) 26(3.95,2.25) 27(3.95,2.75) 28(3.95,3.25) 43(-3.95,3.25) 44(-3.95,2.75) 45(-3.95,2.25) 46(-3.95,1.75) 47(-3.95,1.25) 48(-3.95,0.75) 49(-3.95,0.25) 50(-3.95,-0.25) 51(-3.95,-0.75) 52(-3.95,-1.25) 53(-3.95,-1.75) 54(-3.95,-2.25) 55(-3.95,-2.75) 56(-3.95,-3.25)
  rect 4.369x4.369 smd: PAD(0,0)
R0201
  rect 0.305x0.406 smd: 1(-0.318,0) 2(0.318,0)
R0402
  rect 0.889x0.813 smd: 1(-0.635,0) 2(0.635,0)
R0603
  rect 1.092x1.194 smd: 1(-0.851,0) 2(0.851,0)
SON10_2X2_PAD1_5X0_9
  oval 0.203x0.762 smd: 1(-0.8,-1) 2(-0.4,-1) 3(0,-1) 4(0.4,-1) 5(0.8,-1) 6(0.8,1) 7(0.4,1) 8(0,1) 9(-0.4,1) 10(-0.8,1)
  rect 1.499x0.889 smd: PAD(0,0)
SOT23
  rect 1.016x1.397 smd: 1(-0.94,-1.118) 2(0.94,-1.118) 3(0,1.118)
SOT23_6-2
  rect 0.711x0.991 smd: 1(-0.95,-1.2) 2(0,-1.2) 3(0.95,-1.2) 4(0.95,1.2) 5(0,1.2) 6(-0.95,1.2)
SOT-563
  rect 0.305x0.508 smd: 1(-0.508,-0.699) 2(0,-0.699) 3(0.508,-0.699) 4(0.508,0.699) 5(0,0.699) 6(-0.508,0.699)
SWSML213W98H98
  rect 0.991x1.295 smd: 1(-1.75,-1.948) 2(0,1.948) 3(1.75,-1.948)
SWSMSQ197H165
  rect 1.778x1.27 smd: 1A(-1.905,-1.27) 1B(1.905,-1.27) 2A(-1.905,1.27) 2B(1.905,1.27)
TBGA24
  round 0.33 smd: A2(-2,-1) A3(-2,0) A4(-2,1) A5(-2,2) B1(-1,-2) B2(-1,-1) B3(-1,0) B4(-1,1) B5(-1,2) C1(0,-2) C2(0,-1) C3(0,0) C4(0,1) C5(0,2) D1(1,-2) D2(1,-1) D3(1,0) D4(1,1) D5(1,2) E1(2,-2) E2(2,-1) E3(2,0) E4(2,1) E5(2,2)
TPSMC30
  round 0.762 smd: 1(0,0)
TSML150W160H160
  rect 0.762x1.651 smd: 1(-1.27,1.587) 2(0,1.587) 3(1.27,1.587) 4(1.27,-1.587) 5(0,-1.587) 6(-1.27,-1.587)
TSOT-5
  rect 0.508x1.524 smd: 1(-0.95,-1.17) 2(0,-1.17) 3(0.95,-1.17) 4(0.95,1.17) 5(-0.95,1.17)
unnamed#2
  round 5.207 hole 3.937 unplated: (0,0)
YSML98W79H35
  rect 1.092x0.991 smd: 1(-0.921,-0.72) 2(0.921,-0.72) 3(0.921,0.72) 4(-0.921,0.72)
YSML126W98H39
  rect 1.397x1.194 smd: 1(-1.199,-0.847) 2(1.199,-0.847) 3(1.199,0.847) 4(-1.199,0.847)
YSML126W98H47
  rect 1.397x1.194 smd: 1(-1.2,-0.95) 2(1.2,-0.95) 3(1.2,0.95) 4(-1.2,0.95)

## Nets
0.95V: C44.P(N1) C85.P(N1) C140.1(N1) C141.1(N1) C142.1(N1) C143.1(N1) C148.1(N1) C149.1(N1) C150.1(N1) C151.1(N1) C152.1(N1) C155.1(N1) C156.1(N1) C194.1(N1) C195.1(N1) C258.1(N1) C259.1(N1) C308.1(N1) C309.1(N1) L13.2(N2) R303.2(N2) U1.L11(VCCINT1) U1.L13(VCCINT2) U1.L15(VCCINT3) U1.M12(VCCINT4) U1.M16(VCCBRAM1) U1.N11(VCCINT5) U1.N15(VCCINT6) U1.P12(VCCINT7) U1.P16(VCCBRAM2) U1.R11(VCCINT8) U1.R15(VCCINT9) U1.T12(VCCINT10) U1.T14(VCCINT11) U1.T16(VCCBRAM3) U1.U11(VCCINT12) U1.U13(VCCINT13) U1.U15(VCCINT14) U1.V16(VCCBRAM4) U7.1(VX1)
1.0V: C67.1(N1) E4.1(N1) L5.2(N2) R23.2(N2) U4.10(VOUT1) U7.2(VX2)
1.8V: C69.1(N1) C310.1(N1) C318.1(N1) C347.1(N1) C362.1(N1) E9.1(N1) E10.1(N1) E14.1(N1) L7.2(N2) R25.2(N2) R81.2(N2) U4.22(VOUT3) U7.6(VP1) U19.1(VIN1) U19.2(VIN2) U19.3(VIN3) U19.15(VIN4) U19.16(VIN5) U20.1(VIN1) U20.2(VIN2) U20.3(VIN3) U20.15(VIN4) U20.16(VIN5)
1.8V_EN: U4.24(EN3) U7.23(PDO8)
1.35V: C68.1(N1) E2.1(N1) E3.1(N1) L6.2(N2) R24.2(N2) U4.9(VOUT2) U7.5(VX5)
3.3V: C38.1(N1) C188.1(N1) C199.1(N1) C260.1(N1) E7.1(N1) E8.1(N1) E15.1(N1) E16.1(N1) R33.1(N1) R34.1(N1) U5.6(VDD) U6.5(EN_UVLO) U6.8(VIN) U8.1(VIN) U8.3(EN) U9.1(VOUT) U9.2(SENSE)
3.3V_EN: U7.27(PDO4) U9.5(EN)
3.3V_SEQ: R34.2(N2) R35.1(N1) U7.38(AUX1)
3V3_I2C: C124.1(N1) C134.1(N1) C244.2(N2) C248.1(N1) D3.A(P) R51.1(N1) R52.1(N1) R61.1(N1) R63.1(N1) R65.1(N1) R69.2(N2) R71.2(N2) U21.8(VCCB) U23.4(SENSE/ADJ) U23.5(VOUT) U24.10(VDD) U24.16(VDRIVE) U24.17(PD_N/RST_N)
GND: C1.2(N2) C2.2(N2) C3.2(N2) C4.2(N2) C5.2(N2) C12.2(N2) C13.2(N2) C14.1(N1) C15.2(N2) C16.1(N1) C17.2(N2) C18.2(N2) C19.1(N1) C20.1(N1) C21.2(N2) C22.2(N2) C23.2(N2) C24.2(N2) C27.2(N2) C28.2(N2) C31.2(N2) C36.2(N2) C37.2(N2) C38.2(N2) C39.2(N2) C40.2(N2) C41.2(N2) C42.2(N2) C43.1(N1) C44.N(N2) C49.2(N2) C50.2(N2) C54.2(N2) C55.2(N2) C57.2(N2) C58.2(N2) C59.2(N2) C60.2(N2) C61.2(N2) C62.2(N2) C63.2(N2) C64.2(N2) C65.2(N2) C66.2(N2) C67.2(N2) C68.2(N2) C69.2(N2) C70.2(N2) C71.2(N2) C72.2(N2) C73.2(N2) C74.2(N2) C75.2(N2) C76.2(N2) C77.2(N2) C78.2(N2) C79.2(N2) C80.2(N2) C81.2(N2) C82.2(N2) C83.2(N2) C84.2(N2) C85.N(N2) C86.2(N2) C87.2(N2) C88.2(N2) C89.2(N2) C90.2(N2) C91.2(N2) C92.2(N2) C93.2(N2) C94.2(N2) C95.2(N2) C96.2(N2) C97.2(N2) C98.2(N2) C99.2(N2) C100.2(N2) C101.2(N2) C102.2(N2) C103.2(N2) C104.1(N1) C105.2(N2) C106.2(N2) C107.2(N2) C108.2(N2) C109.2(N2) C110.2(N2) C111.2(N2) C112.2(N2) C113.2(N2) C114.2(N2) C115.2(N2) C116.2(N2) C117.2(N2) C118.2(N2) C119.2(N2) C120.2(N2) C121.2(N2) C122.1(N1) C123.1(N1) C124.2(N2) C125.2(N2) C126.2(N2) C127.2(N2) C128.2(N2) C129.2(N2) C130.2(N2) C131.2(N2) C132.2(N2) C133.2(N2) C134.2(N2) C135.2(N2) C136.2(N2) C137.2(N2) C138.2(N2) C139.2(N2) C140.2(N2) C141.2(N2) C142.2(N2) C143.2(N2) C144.2(N2) C145.2(N2) C146.2(N2) C147.2(N2) C148.2(N2) C149.2(N2) C150.2(N2) C151.2(N2) C152.2(N2) C153.2(N2) C154.2(N2) C155.2(N2) C156.2(N2) C157.2(N2) C158.2(N2) C159.2(N2) C160.2(N2) C161.2(N2) C162.2(N2) C163.2(N2) C164.2(N2) C165.2(N2) C166.2(N2) C167.2(N2) C168.2(N2) C169.2(N2) C170.2(N2) C171.2(N2) C172.2(N2) C173.2(N2) C174.2(N2) C175.2(N2) C176.2(N2) C177.2(N2) C178.2(N2) C179.2(N2) C180.2(N2) C181.2(N2) C182.2(N2) C183.2(N2) C184.2(N2) C185.2(N2) C186.2(N2) C187.2(N2) C188.2(N2) C191.2(N2) C192.2(N2) C193.2(N2) C194.2(N2) C195.2(N2) C196.2(N2) C197.2(N2) C198.2(N2) C199.2(N2) C200.2(N2) C201.2(N2) C202.2(N2) C203.2(N2) C204.2(N2) C205.2(N2) C206.2(N2) C207.2(N2) C208.2(N2) C209.2(N2) C210.2(N2) C211.2(N2) C212.2(N2) C213.2(N2) C214.2(N2) C215.2(N2) C217.2(N2) C218.2(N2) C219.2(N2) C220.2(N2) C221.2(N2) C222.2(N2) C223.2(N2) C224.2(N2) C225.2(N2) C226.2(N2) C227.2(N2) C228.2(N2) C229.2(N2) C230.2(N2) C231.2(N2) C232.2(N2) C233.2(N2) C234.2(N2) C235.2(N2) C236.2(N2) C237.2(N2) C238.2(N2) C239.2(N2) C240.2(N2) C241.2(N2) C243.1(N1) C244.1(N1) C245.2(N2) C246.2(N2) C247.2(N2) C248.2(N2) C249.2(N2) C250.2(N2) C251.2(N2) C252.2(N2) C254.2(N2) C256.2(N2) C258.2(N2) C259.2(N2) C260.2(N2) C301.2(N2) C305.2(N2) C308.2(N2) C309.2(N2) C310.2(N2) C311.2(N2) C312.2(N2) C313.2(N2) C314.2(N2) C315.2(N2) C318.2(N2) C319.2(N2) C320.2(N2) C321.2(N2) C322.2(N2) C323.2(N2) C324.2(N2) C325.2(N2) C326.2(N2) C327.2(N2) C328.2(N2) C329.2(N2) C330.2(N2) C331.2(N2) C332.2(N2) C333.2(N2) C334.2(N2) C335.2(N2) C336.2(N2) C337.2(N2) C340.2(N2) C341.2(N2) C342.2(N2) C343.2(N2) C344.2(N2) C347.2(N2) C348.2(N2) C354.2(N2) C355.2(N2) C356.2(N2) C357.2(N2) C358.2(N2) C359.2(N2) C360.2(N2) C361.2(N2) C362.2(N2) C363.2(N2) C364.2(N2) C365.2(N2) E12.1(N1) J3.6(N6) J3.GND1 J3.GND2 J3.GND3 J3.GND4 JX1.15(N8) JX1.16(N8) JX1.21(N11) JX1.22(N11) JX1.27(N14) JX1.28(N14) JX1.33(N17) JX1.34(N17) JX1.39(N20) JX1.40(N20) JX1.45(N23) JX1.46(N23) JX1.51(N1) JX1.52(N1) JX1.65(N8) JX1.66(N8) JX1.71(N11) JX1.72(N11) JX1.77(N14) JX1.85(N18) JX1.86(N18) JX1.95(N23) JX1.96(N23) JX2.15(N8) JX2.16(N8) JX2.21(N11) JX2.22(N11) JX2.27(N14) JX2.28(N14) JX2.33(N17) JX2.34(N17) JX2.39(N20) JX2.40(N20) JX2.45(N23) JX2.46(N23) JX2.51(N1) JX2.52(N1) JX2.65(N8) JX2.66(N8) JX2.71(N11) JX2.72(N11) JX2.77(N14) JX2.85(N18) JX2.86(N18) JX2.91(N21) JX2.92(N21) JX3.6(N3) JX3.12(N6) JX3.17(N9) JX3.18(N9) JX3.23(N12) JX3.24(N12) JX3.29(N15) JX3.35(N18) JX3.40(N20) JX3.49(N25) JX3.50(N25) JX3.55(N3) JX3.56(N3) JX3.61(N6) JX3.62(N6) JX3.65(N8) JX3.71(N11) JX3.72(N11) JX3.77(N14) JX3.78(N14) JX3.83(N17) JX3.84(N17) JX3.89(N20) JX3.90(N20) JX3.95(N23) JX3.96(N23) JX4.5(N3) JX4.6(N3) JX4.11(N6) JX4.12(N6) JX4.17(N9) JX4.18(N9) JX4.23(N12) JX4.24(N12) JX4.29(N15) JX4.30(N15) JX4.39(N20) JX4.40(N20) JX4.49(N25) JX4.50(N25) JX4.55(N3) JX4.56(N3) JX4.61(N6) JX4.62(N6) JX4.65(N8) JX4.66(N8) JX4.71(N11) JX4.72(N11) JX4.83(N17) JX4.84(N17) JX4.89(N20) JX4.90(N20) JX4.95(N23) JX4.96(N23) M1.GND1 M1.GND2 M1.GND3 M1.GND4 M1.GND5 M1.GND6 M1.GND7 M1.GND8 M1.GND9 M1.GND10 M1.GND11 M1.GND12 M1.GND13 M1.GND14 M1.GND15 M1.GND16 M1.GND17 M1.GND18 M1.GND19 M1.GND20 M1.GND21 M1.GND22 P1.A2(N2A) P1.B2(N2B) Q1.2(S) Q2.2(S) Q3.2(S) Q4.2(S) Q6.2(S) Q14.2(S) R5.2(N2) R12.1(N1) R13.2(N2) R14.2(N2) R20.2(N2) R21.2(N2) R22.2(N2) R26.2(N2) R27.2(N2) R35.2(N2) R38.2(N2) R40.2(N2) R50.2(N2) R53.2(N2) R59.2(N2) R62.2(N2) R64.2(N2) R66.2(N2) R68.2(N2) R74.2(N2) R75.2(N2) R77.2(N2) R78.2(N2) R79.2(N2) R80.2(N2) R101.2(N2) R102.2(N2) R111.1(N1) R116.2(N2) R119.2(N2) R120.2(N2) R125.2(N2) R133.2(N2) R135.2(N2) R165.2(N2) R166.2(N2) R176.2(N2) R191.2(N2) R302.1(N1) RX1A.2(SH1) RX1A.3(SH2) RX1B.2(SH1) RX1B.3(SH2) RX2A.2(SH1) RX2A.3(SH2) RX2B.2(SH1) RX2B.3(SH2) S1.1(NO) S3.1(NO) S4.1(NO) SW1.2A(N3) SW1.2B(N4) T1.1(NC1) T1.2(PRI) T1.5(NC2) T2.1(NC1) T2.2(PRI) T2.5(NC2) T3.1(NC1) T3.2(PRI) T3.5(NC2) T4.1(NC1) T4.2(PRI) T4.5(NC2) T5.1(NC1) T5.2(PRI) T5.5(NC2) T6.1(NC1) T6.2(PRI) T6.5(NC2) T7.1(NC1) T7.2(PRI) T7.5(NC2) T8.1(NC1) T8.2(PRI) T8.5(NC2) TX1A.2(SH1) TX1A.3(SH2) TX1B.2(SH1) TX1B.3(SH2) TX2A.2(SH1) TX2A.3(SH2) TX2B.2(SH1) TX2B.3(SH2) TXM1.2(SH1) TXM1.3(SH2) TXM2.2(SH1) TXM2.3(SH2) U1.A1(GND1) U1.A11(GND2) U1.A21(GND3) U1.AA3(GND6) U1.AA7(GND7) U1.AA9(GND8) U1.AA11(GND4) U1.AA21(GND5) U1.AB1(GND9) U1.AB5(GND11) U1.AB9(GND12) U1.AB18(GND10) U1.AC3(GND15) U1.AC5(MGTXRXN2_111) U1.AC6(MGTXRXP2_111) U1.AC7(GND16) U1.AC9(GND17) U1.AC15(GND13) U1.AC25(GND14) U1.AD1(GND18) U1.AD3(MGTXRXN3_111) U1.AD4(MGTXRXP3_111) U1.AD5(GND21) U1.AD7(MGTXRXN0_111) U1.AD8(MGTXRXP0_111) U1.AD9(GND22) U1.AD12(GND19) U1.AD22(GND20) U1.AE3(GND24) U1.AE5(MGTXRXN1_111) U1.AE6(MGTXRXP1_111) U1.AE7(GND25) U1.AE9(GND26) U1.AE19(GND23) U1.AF1(GND27) U1.AF5(GND30) U1.AF9(GND31) U1.AF16(GND28) U1.AF26(GND29) U1.B8(GND33) U1.B18(GND32) U1.C5(GND36) U1.C15(GND34) U1.C25(GND35) U1.D2(GND38) U1.D12(GND37) U1.D22(GND39) U1.E9(GND41) U1.E19(GND40) U1.F6(GND44) U1.F16(GND42) U1.F26(GND43) U1.G3(GND47) U1.G13(GND45) U1.G23(GND46) U1.H10(GND48) U1.H20(GND49) U1.J7(GND51) U1.J17(GND50) U1.K4(GND54) U1.K14(GND52) U1.K24(GND53) U1.L1(GND55) U1.L10(GND56) U1.L12(GND57) U1.L14(GND58) U1.L16(GND59) U1.L18(GND60) U1.L21(GND61) U1.M9(GND66) U1.M11(GND62) U1.M15(GND63) U1.M17(GND64) U1.M19(GND65) U1.N5(GND72) U1.N10(GND67) U1.N12(GND68) U1.N16(GND69) U1.N18(GND70) U1.N25(GND71) U1.P1(GND73) U1.P2(GND78) U1.P3(GND80) U1.P4(GND81) U1.P5(GND82) U1.P6(GND83) U1.P7(GND84) U1.P9(GND85) U1.P11(GND74) U1.P15(GND75) U1.P17(GND76) U1.P19(GND77) U1.P22(GND79) U1.R3(GND90) U1.R7(GND91) U1.R10(GND86) U1.R12(GND87) U1.R16(GND88) U1.R18(GND89) U1.T1(GND92) U1.T5(GND99) U1.T9(GND100) U1.T11(GND93) U1.T13(GND94) U1.T15(GND95) U1.T17(GND96) U1.T19(GND97) U1.T26(GND98) U1.U3(GND107) U1.U7(GND108) U1.U10(GND101) U1.U12(GND102) U1.U14(GND103) U1.U16(GND104) U1.U18(GND105) U1.U23(GND106) U1.V1(GND109) U1.V5(GND112) U1.V7(GND113) U1.V13(RSVDGND) U1.V17(GND110) U1.V20(GND111) U1.W3(GND114) U1.W7(GND115) U1.Y1(GND116) U1.Y5(GND119) U1.Y7(GND120) U1.Y8(GND121) U1.Y9(GND122) U1.Y14(GND117) U1.Y24(GND118) U2.A9(VSS_1) U2.B1(VSSQ_1) U2.B3(VSS_2) U2.B9(VSSQ_2) U2.D1(VSSQ_3) U2.D8(VSSQ_4) U2.E1(VSS_3) U2.E2(VSSQ_5) U2.E8(VSSQ_6) U2.F9(VSSQ_7) U2.G1(VSSQ_8) U2.G8(VSS_4) U2.G9(VSSQ_9) U2.J2(VSS_5) U2.J8(VSS_6) U2.M1(VSS_7) U2.M9(VSS_8) U2.P1(VSS_9) U2.P9(VSS_10) U2.T1(VSS_11) U2.T9(VSS_12) U3.A9(VSS_1) U3.B1(VSSQ_1) U3.B3(VSS_2) U3.B9(VSSQ_2) U3.D1(VSSQ_3) U3.D8(VSSQ_4) U3.E1(VSS_3) U3.E2(VSSQ_5) U3.E8(VSSQ_6) U3.F9(VSSQ_7) U3.G1(VSSQ_8) U3.G8(VSS_4) U3.G9(VSSQ_9) U3.J2(VSS_5) U3.J8(VSS_6) U3.M1(VSS_7) U3.M9(VSS_8) U3.P1(VSS_9) U3.P9(VSS_10) U3.T1(VSS_11) U3.T9(VSS_12) U4.5(PGND2) U4.14(PGND1) U4.18(AGND) U4.19(PGND3) U4.PAD U5.10(GND) U6.3(GND1) U6.6(GND2) U6.PAD U7.11(AGND) U7.12(REFGND) U7.31(PDOGND) U7.40(GND) U7.PAD(EPAD) U8.2(GND) U9.3(GND1) U9.6(GND2) U9.PAD U10.PAD U11.2(GND1) U11.11(GND2) U11.PAD U13.B3(VSS) U14.4(PGND) U14.8(GND) U14.PAD U15.PAD(GND_FLAG) U16.5(REF2) U17.A4(VSSA26) U17.A6(VSSA01) U17.A12(TX_EXT_LO_IN) U17.B1(VSSA02) U17.B2(VSSA03) U17.B12(VSSA04) U17.C1(RX2C_P) U17.C2(VSSA05) U17.C4(TEST/ENABLE) U17.C7(VSSA06) U17.C8(VSSA07) U17.C9(VSSA08) U17.C10(VSSA09) U17.C11(VSSA10) U17.C12(VSSA11) U17.D1(RX2C_N) U17.D12(VSSD01) U17.F3(VSSA12) U17.F7(VSSD02) U17.F9(VSSD03) U17.F11(VSSD04) U17.G12(VSSD05) U17.H2(VSSA13) U17.H3(VSSA14) U17.H6(VSSA28) U17.H7(VSSD06) U17.H10(VSSD07) U17.J2(VSSA15) U17.K1(RX1C_P) U17.K2(VSSA16) U17.K12(VSSD08) U17.L1(RX1C_N) U17.L2(VSSA17) U17.L3(VSSA18) U17.L7(VSSA19) U17.L8(VSSA20) U17.L9(VSSA21) U17.L10(VSSA22) U17.L11(VSSA23) U17.L12(VSSA24) U17.M4(VSSA27) U17.M6(VSSA25) U18.4(GND1) U18.8(PGND1) U18.9(PGND2) U18.10(PGND3) U18.11(PGND4) U18.12(PGND5) U18.13(PGND6) U18.PAD1(GND2) U19.6(GND) U19.PAD U20.6(GND) U20.PAD U21.4(GND) U22.7(GND) U22.8(GND1) U22.9(OE_N) U22.PAD U23.2(GND) U24.6(GND1) U24.9(GND) U24.PAD Y1.2(GND) Y2.2(GND1) Y2.4(GND2) Y3.2(GND) Y4.2(GND)
VBUS: D1.2(N2) DS1.A(P) P1.A1(N1A) P1.B1(N1B)
VCC-1P35: C86.1(N1) C87.1(N1) C88.1(N1) C89.1(N1) C91.1(N1) C92.1(N1) C94.1(N1) C95.1(N1) C96.1(N1) C97.1(N1) C100.1(N1) C106.1(N1) C107.1(N1) C108.1(N1) C109.1(N1) C112.1(N1) C115.1(N1) C116.1(N1) C117.1(N1) C118.1(N1) C120.1(N1) C192.1(N1) E3.2(N2) R134.2(N2) U2.A1(VDDQ_1) U2.A8(VDDQ_2) U2.B2(VDD_1) U2.C1(VDDQ_3) U2.C9(VDDQ_4) U2.D2(VDDQ_5) U2.D9(VDD_2) U2.E9(VDDQ_6) U2.F1(VDDQ_7) U2.G7(VDD_3) U2.H2(VDDQ_8) U2.H9(VDDQ_9) U2.K2(VDD_4) U2.K8(VDD_5) U2.N1(VDD_6) U2.N9(VDD_7) U2.R1(VDD_8) U2.R9(VDD_9) U3.A1(VDDQ_1) U3.A8(VDDQ_2) U3.B2(VDD_1) U3.C1(VDDQ_3) U3.C9(VDDQ_4) U3.D2(VDDQ_5) U3.D9(VDD_2) U3.E9(VDDQ_6) U3.F1(VDDQ_7) U3.G7(VDD_3) U3.H2(VDDQ_8) U3.H9(VDDQ_9) U3.K2(VDD_4) U3.K8(VDD_5) U3.N1(VDD_6) U3.N9(VDD_7) U3.R1(VDD_8) U3.R9(VDD_9) U14.1(VDDQSNS)
VCC-3P3V: C43.2(N2) C196.1(N1) E7.2(N2) R178.1(N1) R221.1(N1) R222.1(N1) U14.10(VDD)
VCC-3P3V-IO: C41.1(N1) C42.1(N1) C57.1(N1) C184.1(N1) C197.1(N1) D4.A(P) E8.2(N2) J3.4(N4) R4.1(N1) R8.1(N1) R109.1(N1) R167.1(N1) R168.1(N1) R169.2(N2) S1.3(NCP) U1.U8(RSVDVCC3) U1.V8(RSVDVCC2) U1.V12(VCCO_0_1) U1.V14(VCCO_0_2) U1.W8(RSVDVCC1) U11.17(VCCB1) U11.21(VCCB0) U15.20(VDD33) U15.21(VBAT)
VCCO-DDR: C121.1(N1) C125.1(N1) C126.1(N1) C127.1(N1) C128.1(N1) C129.1(N1) C130.1(N1) C131.1(N1) C132.1(N1) C135.1(N1) C136.1(N1) C137.1(N1) C138.1(N1) C139.1(N1) C193.1(N1) E2.2(N2) U1.H25(VCCO_DDR_502_1) U1.J22(VCCO_DDR_502_2) U1.L26(VCCO_DDR_502_3) U1.M23(VCCO_DDR_502_4) U1.N20(VCCO_DDR_502_5) U1.R24(VCCO_DDR_502_6) U1.T21(VCCO_DDR_502_7) U1.V25(VCCO_DDR_502_8) U1.W22(VCCO_DDR_502_9)
VCCO_1P8V: C37.1(N1) C70.1(N1) C71.1(N1) C72.1(N1) C90.1(N1) C93.1(N1) C98.1(N1) C249.1(N1) C250.1(N1) Q12.4(S) U1.A16(VCCO_35_1) U1.B13(VCCO_35_2) U1.E14(VCCO_35_3) U1.F11(VCCO_35_4) U1.H15(VCCO_35_5) U1.J12(VCCO_35_6)
VCCO_1P8V_EN: Q12.3(G) U7.24(PDO7)
VCCO_12: C111.1(N1) C144.1(N1) C146.1(N1) C153.1(N1) C157.1(N1) C160.1(N1) Q11.4(S1) Q11.PAD2(S2) U1.AA16(VCCO_12_1) U1.AB13(VCCO_12_2) U1.AC10(VCCO_12_3) U1.AD17(VCCO_12_4) U1.AE14(VCCO_12_5) U1.AF11(VCCO_12_6)
VCCO_12_13_EN: Q9.3(G) Q11.3(G) U7.29(PDO2)
VCCO_13: C167.1(N1) C169.1(N1) C170.1(N1) C171.1(N1) C185.1(N1) C186.1(N1) C243.2(N2) Q9.4(S1) Q9.PAD2(S2) R57.1(N1) R58.1(N1) U1.AA26(VCCO_13_1) U1.AB23(VCCO_13_2) U1.AC20(VCCO_13_3) U1.AE24(VCCO_13_4) U1.AF21(VCCO_13_5) U1.Y19(VCCO_13_6) U21.1(VCCA)
VCCO_33_34: C15.1(N1) C17.1(N1) C18.1(N1) C27.1(N1) C28.1(N1) C31.1(N1) C99.1(N1) C110.1(N1) C114.1(N1) C145.1(N1) C147.1(N1) C154.1(N1) C246.1(N1) Q10.4(S) U1.A6(VCCO_34_1) U1.B3(VCCO_34_2) U1.C10(VCCO_34_3) U1.D7(VCCO_34_4) U1.E4(VCCO_33_1) U1.F1(VCCO_33_2) U1.G8(VCCO_34_5) U1.H5(VCCO_33_3) U1.J2(VCCO_33_4) U1.K9(VCCO_34_6) U1.L6(VCCO_33_5) U1.M3(VCCO_33_6) U22.14(VCCB)
VCCO_33_34_EN: Q10.3(G) U7.28(PDO3)
VCCPCOM-1P8V: C39.1(N1) C40.1(N1) C54.1(N1) C55.1(N1) C82.1(N1) C83.1(N1) C119.1(N1) C166.1(N1) C168.1(N1) C172.1(N1) C174.1(N1) C175.1(N1) C176.1(N1) C177.1(N1) C179.1(N1) C180.1(N1) C181.1(N1) C182.1(N1) C183.1(N1) C187.1(N1) C198.1(N1) E1.1(N1) E9.2(N2) L12.1(N1) Q5.1(G) Q12.1(D1) Q12.2(D2) Q12.5(D3) Q12.6(D4) R3.1(N1) R6.1(N1) R7.1(N1) R9.1(N1) R28.1(N1) R31.1(N1) R32.1(N1) R36.1(N1) R37.1(N1) R76.1(N1) R194.1(N1) S3.3(NCP) S4.3(NCP) U1.A26(VCCO_MIO0_500_1) U1.B23(VCCO_MIO0_500_2) U1.C20(VCCO_MIO1_501_1) U1.D17(VCCO_MIO1_501_2) U1.E24(VCCO_MIO0_500_3) U1.F21(VCCO_MIO1_501_3) U1.G18(VCCO_MIO1_501_4) U1.K18(VCCO_MIO1_501_5) U1.L19(VCCPAUX1) U1.M10(VCCAUX_IO_G0_1) U1.N9(VCCAUX1) U1.N19(VCCPAUX2) U1.P8(VCCAUX2) U1.P10(VCCAUX_IO_G0_2) U1.R9(VCCAUX3) U1.R19(VCCPAUX3) U1.T8(VCCAUX4) U1.T10(VCCAUX_IO_G0_3) U1.U9(VCCAUX5) U1.U19(VCCPAUX4) U1.V6(MGTVCCAUX) U1.V10(VCCAUX6) U11.5(VCCA) U13.B4(VCC) U15.8(REFSEL0) U15.11(REFSEL1) U15.14(REFSEL2) U15.28(VDD18_1) U15.30(VDD18_2) U15.32(VDDIO) Y1.4(VDD) Y3.4(VDD)
VCCPINT: C159.1(N1) C161.1(N1) C162.1(N1) C163.1(N1) C164.1(N1) C173.1(N1) C191.1(N1) E4.2(N2) U1.L17(VCCPINT1) U1.N17(VCCPINT2) U1.P18(VCCPINT3) U1.R17(VCCPINT4) U1.T18(VCCPINT5) U1.U17(VCCPINT6)
VDD_INTERFACE: C245.1(N1) C348.1(N1) C354.1(N1) C355.1(N1) C356.1(N1) C357.1(N1) C363.1(N1) E10.2(N2) R306.2(N2) U17.H12(VDD_INTERFACE) U22.1(VCCA)
VDDA_GPO: C319.1(N1) C358.1(N1) C359.1(N1) C360.1(N1) C361.1(N1) E11.2(N2) R67.1(N1) U17.B8(VDDA_GPO)
VDDA_GPO_PWR: C200.1(N1) E11.1(N1) JX4.9(N5) U6.1(VOUT) U6.2(SENSE_ADJ)
VDDCAP: C205.1(N1) R30.1(N1) R39.1(N1) U7.39(VDDCAP)
VIN: C36.1(N1) C61.1(N1) C62.1(N1) C65.1(N1) C66.1(N1) C301.1(N1) C364.1(N1) C365.1(N1) Q13.4(S1) Q13.PAD2(S2) R29.1(N1) R43.1(N1) R56.1(N1) TP2.1(N1) U4.3(VIN2) U4.13(MODE) U4.16(VIN1) U4.17(AVIN) U4.21(VIN3) U9.8(VIN) U18.16(PVIN1) U18.17(PVIN2) U18.18(PVIN3) U18.19(PVIN4)
VIN_EN: Q13.3(G) U7.30(PDO1)
1P3_SUPPLY_A: C312.1(N1) C313.1(N1) C314.1(N1) C315.1(N1) C320.1(N1) C321.1(N1) C322.1(N1) C323.1(N1) C326.1(N1) C327.1(N1) C328.1(N1) C329.1(N1) U17.B9(VDDA1P3_TX_LO) U17.B10(VDDA1P3_TX_VCO_LDO) U17.E2(VDDA1P3_RX_LO) U17.F2(VDDA1P3_RX_VCO_LDO) U17.J3(VDDA1P3_RX_SYNTH) U17.K3(VDDA1P3_TX_SYNTH) U19.9(SENSE) U19.10(VOUT1) U19.11(VOUT2) U19.12(VOUT3) U19.13(VOUT4) U19.14(VOUT5) U24.18(VIN0)
1P3_SUPPLY_B: C1.1(N1) C2.1(N1) C3.1(N1) C4.1(N1) C14.2(N2) C16.2(N2) C19.2(N2) C20.2(N2) C21.1(N1) C22.1(N1) C23.1(N1) C24.1(N1) C324.1(N1) C325.1(N1) C330.1(N1) C331.1(N1) C332.1(N1) C333.1(N1) C334.1(N1) C335.1(N1) C336.1(N1) C337.1(N1) C341.1(N1) C342.1(N1) C343.1(N1) C344.1(N1) L1.1(N1) L2.1(N1) L3.1(N1) L4.1(N1) L8.1(N1) L9.1(N1) L10.1(N1) L11.1(N1) U17.D2(VDDA1P3_RX_RF) U17.D3(VDDA1P3_RX_TX) U17.E3(VDDA1P3_TX_LO_BUFFER) U17.F12(VDDD1P3_DIG) U17.K4(VDDA1P3_BB) U20.9(SENSE) U20.10(VOUT1) U20.11(VOUT2) U20.12(VOUT3) U20.13(VOUT4) U20.14(VOUT5) U24.19(VIN1)
9361_XTAL: C165.1(N1) C216.2(N2) U17.M12(XTALN)
AD9361_CLK: JX4.63(N7) R5.1(N1) U5.1(S1A)
AUXADC: JX4.7(N4) U17.L5(AUXADC)
AUXDAC1: JX4.8(N4) U17.B3(AUXDAC1)
AUXDAC2: JX4.10(N5) U17.C3(AUXDAC2)
CARRIER_RESET: JX1.6(N3) Q5.3(D) R8.2(N2)
CTRL_IN0: U17.C5(CTRL_IN0) U22.2(A0)
CTRL_IN1: U17.C6(CTRL_IN1) U22.3(A1)
CTRL_IN2: U17.D6(CTRL_IN2) U22.4(A2)
CTRL_IN3: U17.D5(CTRL_IN3) U22.5(A3)
DDR3_A0: R136.1(N1) U1.K22(PS_DDR_A0_502) U2.N3(A0) U3.N3(A0)
DDR3_A1: R137.1(N1) U1.K20(PS_DDR_A1_502) U2.P7(A1) U3.P7(A1)
DDR3_A2: R138.1(N1) U1.N21(PS_DDR_A2_502) U2.P3(A2) U3.P3(A2)
DDR3_A3: R139.1(N1) U1.L22(PS_DDR_A3_502) U2.N2(A3) U3.N2(A3)
DDR3_A4: R140.1(N1) U1.M20(PS_DDR_A4_502) U2.P8(A4) U3.P8(A4)
DDR3_A5: R141.1(N1) U1.N22(PS_DDR_A5_502) U2.P2(A5) U3.P2(A5)
DDR3_A6: R143.1(N1) U1.L20(PS_DDR_A6_502) U2.R8(A6) U3.R8(A6)
DDR3_A7: R144.1(N1) U1.J21(PS_DDR_A7_502) U2.R2(A7) U3.R2(A7)
DDR3_A8: R145.1(N1) U1.T20(PS_DDR_A8_502) U2.T8(A8) U3.T8(A8)
DDR3_A9: R146.1(N1) U1.U20(PS_DDR_A9_502) U2.R3(A9) U3.R3(A9)
DDR3_A10: R147.1(N1) U1.M22(PS_DDR_A10_502) U2.L7(A10/AP) U3.L7(A10/AP)
DDR3_A11: R148.1(N1) U1.H21(PS_DDR_A11_502) U2.R7(A11) U3.R7(A11)
DDR3_A12: R149.1(N1) U1.P20(PS_DDR_A12_502) U2.N7(A12/BC#) U3.N7(A12/BC#)
DDR3_A13: R150.1(N1) U1.J20(PS_DDR_A13_502) U2.T3(A13) U3.T3(A13)
DDR3_A14: R151.1(N1) U1.R20(PS_DDR_A14_502) U2.T7(A14) U3.T7(A14)
DDR3_BA0: R152.1(N1) U1.U22(PS_DDR_BA0_502) U2.M2(BA0) U3.M2(BA0)
DDR3_BA1: R153.1(N1) U1.T22(PS_DDR_BA1_502) U2.N8(BA1) U3.N8(BA1)
DDR3_BA2: R154.1(N1) U1.R22(PS_DDR_BA2_502) U2.M3(BA2) U3.M3(BA2)
DDR3_CAS#: R159.1(N1) U1.Y23(PS_DDR_CAS_B_502) U2.K3(CAS#) U3.K3(CAS#)
DDR3_CK_N: R142.2(N2) U1.P21(PS_DDR_CKN_502) U2.K7(CK#) U3.K7(CK#)
DDR3_CK_P: R142.1(N1) U1.R21(PS_DDR_CKP_502) U2.J7(CK) U3.J7(CK)
DDR3_CKE: R160.1(N1) U1.U21(PS_DDR_CKE_502) U2.K9(CKE) U3.K9(CKE)
DDR3_CS#: R163.1(N1) U1.Y21(PS_DDR_CS_B_502) U2.L2(CS#) U3.L2(CS#)
DDR3_DM0: U1.G24(PS_DDR_DM0_502) U2.E7(LDM)
DDR3_DM1: U1.K25(PS_DDR_DM1_502) U2.D3(UDM)
DDR3_DM2: U1.P26(PS_DDR_DM2_502) U3.E7(LDM)
DDR3_DM3: U1.V26(PS_DDR_DM3_502) U3.D3(UDM)
DDR3_DQ0: U1.J26(PS_DDR_DQ0_502) U2.E3(DQ0)
DDR3_DQ1: U1.F25(PS_DDR_DQ1_502) U2.F7(DQ1)
DDR3_DQ2: U1.J25(PS_DDR_DQ2_502) U2.F2(DQ2)
DDR3_DQ3: U1.G26(PS_DDR_DQ3_502) U2.F8(DQ3)
DDR3_DQ4: U1.H26(PS_DDR_DQ4_502) U2.H3(DQ4)
DDR3_DQ5: U1.H23(PS_DDR_DQ5_502) U2.H8(DQ5)
DDR3_DQ6: U1.J24(PS_DDR_DQ6_502) U2.G2(DQ6)
DDR3_DQ7: U1.J23(PS_DDR_DQ7_502) U2.H7(DQ7)
DDR3_DQ8: U1.K26(PS_DDR_DQ8_502) U2.D7(DQ8)
DDR3_DQ9: U1.L23(PS_DDR_DQ9_502) U2.C3(DQ9)
DDR3_DQ10: U1.M26(PS_DDR_DQ10_502) U2.C8(DQ10)
DDR3_DQ11: U1.K23(PS_DDR_DQ11_502) U2.C2(DQ11)
DDR3_DQ12: U1.M25(PS_DDR_DQ12_502) U2.A7(DQ12)
DDR3_DQ13: U1.N24(PS_DDR_DQ13_502) U2.A2(DQ13)
DDR3_DQ14: U1.M24(PS_DDR_DQ14_502) U2.B8(DQ14)
DDR3_DQ15: U1.N23(PS_DDR_DQ15_502) U2.A3(DQ15)
DDR3_DQ16: U1.R26(PS_DDR_DQ16_502) U3.E3(DQ0)
DDR3_DQ17: U1.P24(PS_DDR_DQ17_502) U3.F7(DQ1)
DDR3_DQ18: U1.N26(PS_DDR_DQ18_502) U3.F2(DQ2)
DDR3_DQ19: U1.P23(PS_DDR_DQ19_502) U3.F8(DQ3)
DDR3_DQ20: U1.T24(PS_DDR_DQ20_502) U3.H3(DQ4)
DDR3_DQ21: U1.T25(PS_DDR_DQ21_502) U3.H8(DQ5)
DDR3_DQ22: U1.T23(PS_DDR_DQ22_502) U3.G2(DQ6)
DDR3_DQ23: U1.R23(PS_DDR_DQ23_502) U3.H7(DQ7)
DDR3_DQ24: U1.V24(PS_DDR_DQ24_502) U3.D7(DQ8)
DDR3_DQ25: U1.U26(PS_DDR_DQ25_502) U3.C3(DQ9)
DDR3_DQ26: U1.U24(PS_DDR_DQ26_502) U3.C8(DQ10)
DDR3_DQ27: U1.U25(PS_DDR_DQ27_502) U3.C2(DQ11)
DDR3_DQ28: U1.W26(PS_DDR_DQ28_502) U3.A7(DQ12)
DDR3_DQ29: U1.Y25(PS_DDR_DQ29_502) U3.A2(DQ13)
DDR3_DQ30: U1.Y26(PS_DDR_DQ30_502) U3.B8(DQ14)
DDR3_DQ31: U1.W23(PS_DDR_DQ31_502) U3.A3(DQ15)
DDR3_DQS0_N: U1.G25(PS_DDR_DQS_N0_502) U2.G3(LDQS#)
DDR3_DQS0_P: U1.H24(PS_DDR_DQS_P0_502) U2.F3(LDQS)
DDR3_DQS1_N: U1.L25(PS_DDR_DQS_N1_502) U2.B7(UDQS#)
DDR3_DQS1_P: U1.L24(PS_DDR_DQS_P1_502) U2.C7(UDQS)
DDR3_DQS2_N: U1.R25(PS_DDR_DQS_N2_502) U3.G3(LDQS#)
DDR3_DQS2_P: U1.P25(PS_DDR_DQS_P2_502) U3.F3(LDQS)
DDR3_DQS3_N: U1.W25(PS_DDR_DQS_N3_502) U3.B7(UDQS#)
DDR3_DQS3_P: U1.W24(PS_DDR_DQS_P3_502) U3.C7(UDQS)
DDR3_ODT: R162.1(N1) U1.Y22(PS_DDR_ODT_502) U2.K1(ODT) U3.K1(ODT)
DDR3_RAS#: R156.1(N1) U1.V23(PS_DDR_RAS_B_502) U2.J3(RAS#) U3.J3(RAS#)
DDR3_RST#: R133.1(N1) U1.H22(PS_DDR_DRST_B_502) U2.T2(RESET#) U3.T2(RESET#)
DDR3_WE#: R155.1(N1) U1.V22(PS_DDR_WE_B_502) U2.L3(WE#) U3.L3(WE#)
DX_0_N: JX1.100(N25) U1.R13(DXN_0)
DX_0_P: JX1.98(N24) U1.R14(DXP_0)
ETH_MD1_N: JX3.53(N2) U10.27(MDIN(0))
ETH_MD1_P: JX3.51(N1) U10.28(MDIP(0))
ETH_MD2_N: JX3.54(N2) U10.23(MDIN(1))
ETH_MD2_P: JX3.52(N1) U10.24(MDIP(1))
ETH_MD3_N: JP2.1(A) U10.21(MDIN(2))
ETH_MD3_P: JP1.1(A) U10.22(MDIP(2))
ETH_MD4_N: JP4.1(A) U10.17(MDIN(3))
ETH_MD4_P: JP3.1(A) U10.18(MDIP(3))
ETH_PHY_LED0: JX3.47(N24) R18.2(N2)
ETH_PHY_LED1: JX3.48(N24) R17.2(N2)
FB0V95: R49.2(N2) R302.2(N2) R303.1(N1) U18.2(FB)
FB1V0: R20.1(N1) R23.1(N1) R47.2(N2) U4.11(FB1)
FB1V8: R22.1(N1) R25.1(N1) R46.2(N2) U4.23(FB3)
FB1V35: R21.1(N1) R24.1(N1) R48.2(N2) U4.8(FB2)
FB_0V95: C215.1(N1) R45.2(N2) R49.1(N1)
FB_1V0: C209.1(N1) R42.2(N2) R47.1(N1)
FB_1V8: C207.1(N1) R41.2(N2) R46.1(N1)
FB_1V35: C213.1(N1) R44.2(N2) R48.1(N1)
FPGA_DONE: JX1.8(N4) R172.2(N2) U1.W9(DONE_0)
FPGA_VBATT: JX1.7(N4) R9.2(N2) U1.V15(VCCBATT_0) U24.20(VIN2)
GPO0: JX4.1(N1) U17.B7(GPO_0)
GPO1: JX4.2(N1) U17.B6(GPO_1)
GPO2: JX4.3(N2) U17.B5(GPO_2)
GPO3: JX4.4(N2) U17.B4(GPO_3)
INIT_B_0_JX2_09: JX2.9(N5) R168.2(N2) U1.R8(INIT_B_0)
IO_00_12_JX4: JX4.14(N7) U1.W14(IO_0_12)
IO_00_13_JX2: JX2.13(N7) U1.V19(IO_0_13)
IO_00_33_JX1: JX1.9(N5) U1.L9(IO_0_VRN_33)
IO_00_34_AD9361_CLKSEL: Q6.1(G) R54.1(N1) U1.K11(IO_0_VRN_34)
IO_00_35_AD9361_RST: U1.H16(IO_0_VRN_35) U17.K5(RESETB)
IO_25_12_JX4: JX4.16(N8) U1.W17(IO_25_12)
IO_25_13_JX2: JX2.14(N7) U1.V18(IO_25_13)
IO_25_33_JX1: JX1.10(N5) U1.N8(IO_25_VRP_33)
IO_25_34_JX4: JX4.64(N7) U1.K10(IO_25_VRP_34)
IO_25_35_AD9361_CLKOUT: U1.K12(IO_25_VRP_35) U17.J6(CLK_OUT)
IO_L01_12_JX3_N: JX3.22(N11) U1.Y11(IO_L1N_T0_12)
IO_L01_12_JX3_P: JX3.20(N10) U1.Y12(IO_L1P_T0_12)
IO_L01_13_JX2_N: JX2.3(N2) U1.AB25(IO_L1N_T0_13)
